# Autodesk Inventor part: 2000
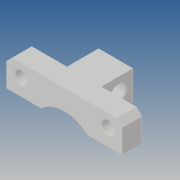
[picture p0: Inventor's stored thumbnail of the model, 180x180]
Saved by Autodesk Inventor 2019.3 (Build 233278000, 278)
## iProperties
Created: 2013-07
Part Number: 2000
Material: Ogólny
Document SubType Name: Modeling
Designer: CADENGINEERING4
Density: 1 g/cm^3
Appearance: Domyślna
Author: CADENGINEERING4
Revision Number: ÈÎºÎ
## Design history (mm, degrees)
feature "µ¹½Ç2"
sketch "Szkic1"
  geometry: C1 r 6 at (15.5, 9) reference; C2 r 6.491 at (15.5, 9); C3 r 6 at (-34.5, 9) reference; C4 r 6.702 at (-34.5, 9)
  constraints: 2 centre point, 2 coincident
sketch "Szkic2"
  geometry: L1 (0, 16)-(19.5, 16) reference; L2 (-38.5, 16)-(-19, 16) reference; L3 (-41.5, 0)-(-41.5, 13) reference; C1 r 3.4 at (14.5, 9); C2 r 3.4 at (-33.5, 9)
  constraints: 2 centre point
  dimensions: "d0" = 6.8 diameter of C1; "d1" = 6.8 diameter of C2; "d2" = 7 distance from line of L1 C1.centre; "d3" = 7 distance from line of L2 C2.centre; "d4" = 48 distance of C2.centre C1.centre; "d5" = 8 distance from line of L3 C2.centre
extrude "Wyciągnięcie proste1" join sketch "Szkic1" stored distance "d6" = 10; taper "d7" = 0 deg
hole "Otwór1" sketch "Szkic2" diameter "d8" = 6.8; stored, may be unused: countersink angle "d12" = 90 deg, drill point angle "d14" = 0 deg; dims "d9" = 24, "d10" = 11, "d11" = 6.5, "d13" = 11
chamfer "Faza1" distance "d15" = 0.5; stored, may be unused: second distance "d16" = 2, angle "d17" = 45 deg
node "Bryła1"
